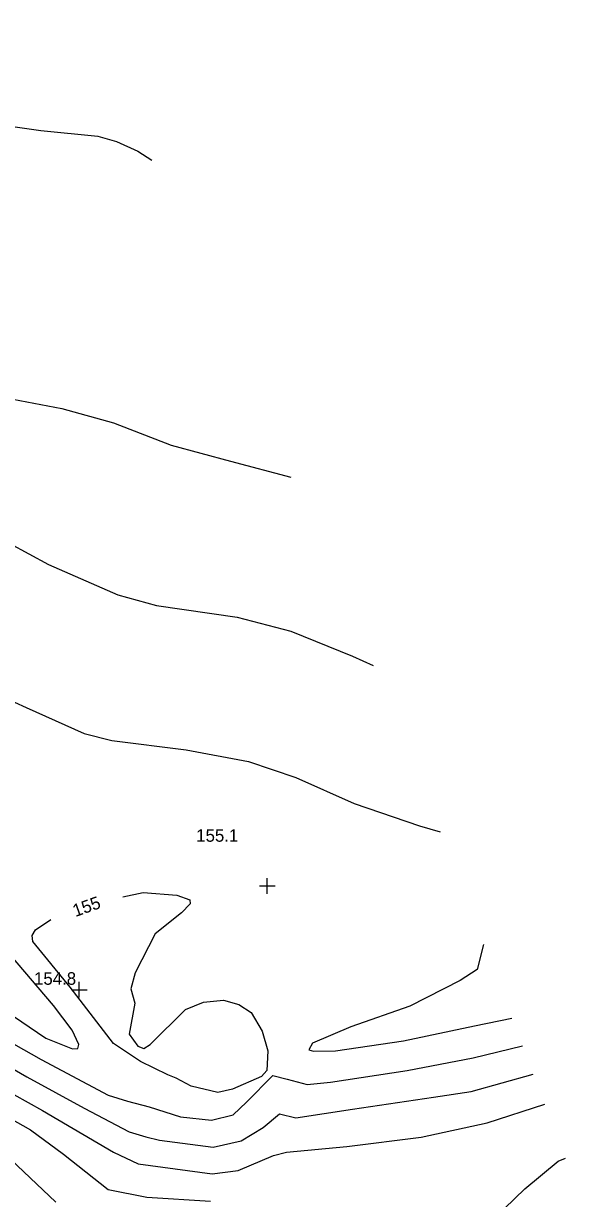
# Model space of a CAD drawing. Extents: x 1467615 to 2003689, y 770235 to 1108726.
# Drawn here: x 2002808.7 to 2002894.9, y 770996.7 to 771183.5 of the extents above; entities that cross this region are included whole.
import ezdxf

# ---------------------------------------------------------------- set-up
doc = ezdxf.new("R2010")
doc.units = 0
for name, color, linetype in [('RD_DTM_Major1', 7, 'Continuous'), ('RD_DTM_Major1_Lbl', 7, 'Continuous'), ('RD_DTM_Minor1', 7, 'Continuous'), ('RD_DTM_Spot_Elev', 7, 'Continuous')]:
    doc.layers.add(name, color=color, linetype=linetype)

msp = doc.modelspace()

# ---------------------------------------------------------------- linework, layer by layer
at = {"layer": 'RD_DTM_Major1'}
for points in [[(2002824.49, 771044.65), (2002827.72, 771045.37), (2002833.09, 771044.94), (2002835.14, 771044.17), (2002835.18, 771043.56), (2002833.82, 771042.13), (2002829.61, 771038.76), (2002826.47, 771032.6), (2002825.75, 771030.06), (2002826.4, 771027.79), (2002825.52, 771022.82), (2002826.86, 771020.95), (2002827.82, 771020.54), (2002828.84, 771021.18), (2002834.47, 771026.78), (2002837.31, 771027.95), (2002840.48, 771028.22), (2002842.93, 771027.57), (2002844.92, 771026.27), (2002846.67, 771023.34), (2002847.53, 771020.19), (2002847.38, 771017.07), (2002846.56, 771016.1), (2002841.91, 771014.08), (2002839.61, 771013.59), (2002835.36, 771014.57), (2002832.98, 771015.82), (2002831.64, 771016.4), (2002827.28, 771018.51), (2002822.98, 771021.38), (2002816.12, 771030.29), (2002810.18, 771037.56), (2002810.07, 771038.53), (2002810.57, 771039.44), (2002813.04, 771041.04)], [(2002786.5, 771039.62), (2002788.08, 771037.92), (2002790.95, 771035.07), (2002799.18, 771026.28), (2002802.22, 771024.22), (2002804.24, 771022.91), (2002811.47, 771018.79), (2002822.16, 771013.15), (2002825.23, 771012.19), (2002828.7, 771011.27), (2002833.66, 771009.71), (2002838.59, 771009.18), (2002842.06, 771010.01), (2002844.15, 771012.04), (2002848.36, 771016.27), (2002850.64, 771015.7), (2002853.81, 771014.83), (2002857.5, 771015.21), (2002869.71, 771017.09), (2002880.21, 771019.09), (2002888.07, 771020.96)]]:
    msp.add_lwpolyline(points, dxfattribs=at)
at = {"layer": 'RD_DTM_Minor1'}
for points in [[(2002813.97, 771285.15), (2002805.78, 771270.5), (2002798.32, 771259.18), (2002792.61, 771248.85), (2002784.19, 771235.97), (2002777.35, 771225.35), (2002772.26, 771212.03), (2002768.49, 771202.57), (2002768.28, 771200.15), (2002769.28, 771192.91), (2002772.52, 771180.14), (2002774.47, 771174.75), (2002775.24, 771174.34), (2002781.28, 771172.81), (2002795.1, 771169.47), (2002801.77, 771167.82), (2002811.44, 771166.48), (2002820.52, 771165.55), (2002823.48, 771164.73), (2002826.87, 771163.2), (2002829.11, 771161.75)], [(2002731.85, 771192.22), (2002730.65, 771183.33), (2002731.05, 771179.78), (2002732.14, 771177.5), (2002736.49, 771172.77), (2002739.98, 771170.09), (2002742.72, 771167.99), (2002745.78, 771165.28), (2002750.52, 771162.57), (2002756.45, 771159.38), (2002760.03, 771156.26), (2002767.35, 771147.41), (2002771.45, 771142.45), (2002775.26, 771138.28), (2002778.39, 771135.91), (2002787.39, 771130.91), (2002800.48, 771124.94), (2002803.6, 771124.38), (2002814.8, 771122.28), (2002822.99, 771120), (2002832.19, 771116.44), (2002841.62, 771113.89), (2002851.21, 771111.38)], [(2002803.21, 771102.56), (2002812.67, 771097.5), (2002823.69, 771092.66), (2002829.83, 771090.97), (2002842.65, 771089.1), (2002851.22, 771086.87), (2002861.02, 771082.92), (2002864.34, 771081.45)], [(2002797.94, 771079.86), (2002809.12, 771074.78), (2002818.33, 771070.61), (2002822.73, 771069.53), (2002834.56, 771068.01), (2002844.49, 771066.18), (2002852.01, 771063.65), (2002861.29, 771059.49), (2002871.66, 771055.94), (2002874.99, 771054.99)], [(2002881.87, 771037.1), (2002880.86, 771033.13), (2002878.18, 771031.39), (2002870.13, 771027.31), (2002860.74, 771024), (2002854.66, 771021.4), (2002854.09, 771020.35), (2002854.83, 771020.15), (2002858.3, 771020.19), (2002869.12, 771021.78), (2002880.41, 771024.14), (2002886.38, 771025.36)], [(2002805.75, 771026.58), (2002812.23, 771022.22), (2002816.5, 771020.49), (2002817.32, 771020.56), (2002817.47, 771021.21), (2002816.41, 771023.48), (2002813.48, 771027.42), (2002806.44, 771035.63)], [(2002801.1, 771020.7), (2002809.21, 771016.06), (2002818.35, 771011.06), (2002825.52, 771007.33), (2002828.14, 771006.52), (2002830.3, 771005.97), (2002838.86, 771004.9), (2002843.33, 771005.88), (2002846.8, 771008.01), (2002849.39, 771010.16), (2002852.02, 771009.53), (2002861, 771010.9), (2002873.91, 771012.81), (2002879.89, 771013.71), (2002889.78, 771016.5)], [(2002802.55, 771015.79), (2002811.71, 771010.72), (2002823.01, 771004.1), (2002826.93, 771002.24), (2002838.7, 771000.63), (2002842.83, 771001.15), (2002848.46, 771003.53), (2002850.53, 771004.06), (2002860.1, 771004.96), (2002871.94, 771006.45), (2002882.45, 771008.76), (2002891.61, 771011.73)], [(2002801.09, 771012.53), (2002809.81, 771007.63), (2002815.07, 771003.77), (2002822.13, 770998.14), (2002828.29, 770996.95), (2002838.46, 770996.29)], [(2002805.64, 771003.89), (2002813.81, 770996.15)], [(2002880.3, 770990.36), (2002888.46, 770998.25), (2002893.75, 771002.66), (2002894.92, 771003.13)]]:
    msp.add_lwpolyline(points, dxfattribs=at)
at = {"layer": 'RD_DTM_Spot_Elev'}
for p, q in [((2002847.46, 771045.15), (2002847.46, 771047.65)), ((2002846.21, 771046.4), (2002848.71, 771046.4)), ((2002817.56, 771028.64), (2002817.56, 771031.14)), ((2002816.31, 771029.89), (2002818.81, 771029.89))]:
    msp.add_line(p, q, dxfattribs=at)

# ---------------------------------------------------------------- texts
at = {"layer": 'RD_DTM_Major1_Lbl'}
msp.add_text('155', height=2, rotation=19.7876, dxfattribs=at).set_placement((2002816.94, 771041.44))
at = {"layer": 'RD_DTM_Spot_Elev'}
for s, p in [('155.1', (2002836.16, 771053.42)), ('154.8', (2002810.36, 771030.69))]:
    msp.add_text(s, height=2, dxfattribs=at).set_placement(p)

doc.saveas('drawing.dxf')
